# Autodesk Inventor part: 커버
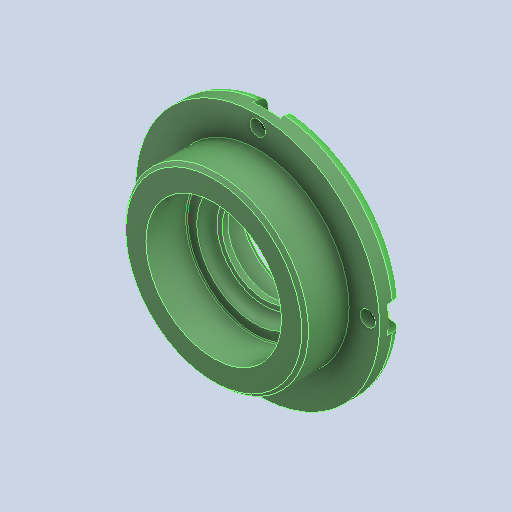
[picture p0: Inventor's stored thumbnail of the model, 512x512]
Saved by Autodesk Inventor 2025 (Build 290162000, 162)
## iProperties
Created: 2024-07
Part Number: 커버
Material: 강철, 연강
Document SubType Name: Modeling
Designer: hsj03
Density: 7.86 g/cm^3
Appearance: 기본값
Company: 한국ATC센터
Author: jhkim
Revision Number: 1
Sending System: Autodesk Inventor 2025
Preprocessor: ST-DEVELOPER v20
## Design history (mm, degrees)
feature "솔리드1"
node "솔리드2"
